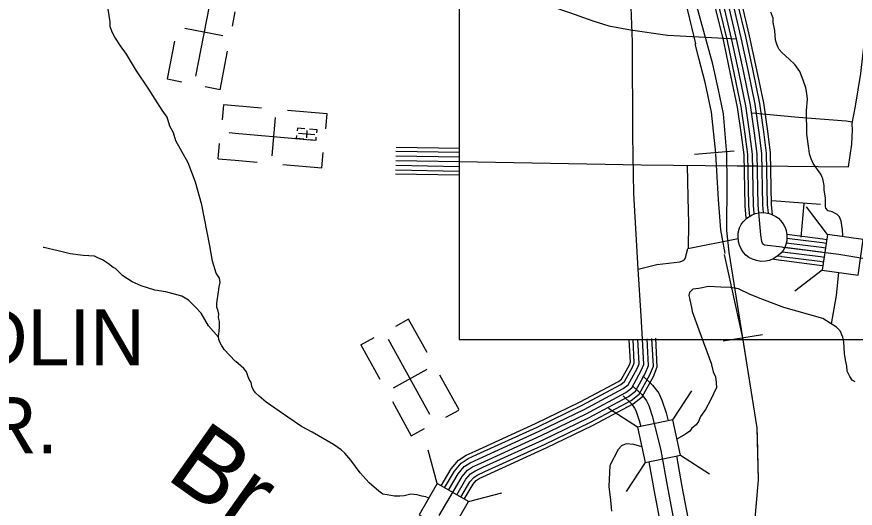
# Model space of a CAD drawing. Extents: x 1551132 to 1791609, y 378168 to 563823.
# Drawn here: x 1670772 to 1676283, y 417031 to 420262 of the extents above; entities that cross this region are included whole.
import ezdxf

# ---------------------------------------------------------------- set-up
doc = ezdxf.new("R2010")
doc.units = 0
for name, color, linetype in [('DESIGN - CONTOURS - Intermediate with optional Text', 7, 'Continuous'), ('DESIGN - DRAINAGE - Bridges and Cross Drains Size Text', 7, 'Continuous'), ('DESIGN - ROW - Right-of-Way and Easement Labels', 7, 'Continuous'), ('DESIGN - ROW - Right-of-Way Linework', 7, 'Continuous'), ('DESIGN - TRANSPORTATION - Text', 7, 'Continuous'), ('DESIGN - UTILITIES - Cable (Underground) with Text', 7, 'Continuous'), ('SURVEY - CONTOURS - Index with Text', 7, 'Continuous'), ('SURVEY - CONTROL with Text', 7, 'Continuous'), ('SURVEY - DRAINAGE - Storm Sewer', 7, 'Continuous'), ('SURVEY - PROPERTY - Owners', 7, 'Continuous'), ('SURVEY - TRANSPORTATION - Roads', 7, 'Continuous'), ('SURVEY - VEGETATION - Features with Text', 7, 'Continuous')]:
    doc.layers.add(name, color=color, linetype=linetype)

msp = doc.modelspace()

# ---------------------------------------------------------------- linework, layer by layer
at = {"layer": 'DESIGN - CONTOURS - Intermediate with optional Text'}
for p, q in [((1675486.076, 419377.968), (1675226.932, 419357.05)), ((1675672.062, 418170.744), (1675415.335, 418129.685))]:
    msp.add_line(p, q, dxfattribs=at)
for points in [[(1675453.401, 418714.959), (1675438.401, 418857.054), (1675440.785, 419175.754), (1675438.56, 419361.426), (1675417.361, 419624.074), (1675385.011, 419780.695), (1675346.787, 419949.399), (1675252.39, 420293.033), (1675130.901, 420723.111), (1675084.952, 420917.95), (1675036.87, 421100.788), (1674986.772, 421281.651), (1674904.149, 421603.118), (1674796.101, 421980.952), (1674652.038, 422545.509), (1674573.44, 422868.926), (1674549.074, 423023.446), (1674520.9, 423196.043), (1674514.859, 423378.389), (1674515.025, 423580.703), (1674521.675, 423827.001), (1674529.617, 424193.477), (1674544.942, 425060.633), (1674568.509, 426136.02)], [(1675234.94, 420083.803), (1675182.025, 420302.134), (1675092.735, 420679.243)], [(1675367.228, 419364.317), (1675337.462, 419635.574), (1675297.78, 419820.821), (1675254.79, 419989.525), (1675231.632, 420083.803)], [(1675426.752, 418706.025), (1675400.294, 418861.504), (1675383.761, 419059.984), (1675367.228, 419361.009)], [(1675359.601, 414899.125), (1675337.41, 415069.646), (1675319.269, 415244.126), (1675316.728, 415380.363), (1675325.294, 415618.636), (1675345.61, 415832.725), (1675377.31, 415988.595), (1675442.158, 416248.244), (1675547.956, 416593.545), (1675612.388, 416812.05), (1675647.629, 417217.186), (1675638.121, 417559.67), (1675453.401, 418714.959)], [(1675543.699, 418150.211), (1675423.443, 418699.408)], [(1675639.838, 417497.718), (1675638.121, 417559.67), (1675543.699, 418150.211)], [(1675614.755, 416839.243), (1675647.629, 417217.186), (1675639.838, 417497.718)]]:
    msp.add_lwpolyline(points, dxfattribs=at)
at = {"layer": 'DESIGN - ROW - Right-of-Way Linework'}
msp.add_lwpolyline([(1673679.553, 422339.845), (1673679.551, 418141.276), (1676663.072, 418141.278), (1676663.074, 421138.773)], dxfattribs=at)
at = {"layer": 'DESIGN - TRANSPORTATION - Text'}
for points in [[(1672208.21, 417998.48), (1672135.828, 418074.648), (1672118.154, 418102.899), (1672108.337, 418119.041), (1672100.596, 418141.167), (1672096.804, 418159.234), (1672101.221, 418195.227), (1672103.554, 418223.236), (1672103.971, 418259.278), (1672098.271, 418285.387), (1672100.529, 418307.388), (1672092.854, 418335.514), (1672087.038, 418351.614), (1672087.363, 418379.64), (1672098.229, 418453.608), (1672102.629, 418487.593), (1672108.954, 418515.552), (1672105.279, 418543.636), (1672081.647, 418575.97), (1672058.555, 418654.355), (1672041.739, 418756.7), (1671988.857, 419025.698), (1671946.575, 419174.419), (1671898.035, 419301.181), (1671849.069, 419391.908), (1671817.695, 419446.359), (1671802.295, 419498.619), (1671778.804, 419542.97), (1671759.48, 419601.28), (1671728.005, 419647.731), (1671635.666, 419793.06), (1671558.959, 419906.155), (1671492.228, 420017.124), (1671452.854, 420071.684), (1671415.496, 420128.219), (1671399.863, 420160.453), (1671386.305, 420198.671), (1671384.655, 420228.73), (1671373.606, 420310.974)], [(1676202.792, 418816.337), (1676201.467, 418823.787), (1676198.375, 418861.571), (1676191.025, 418917.739), (1676179.351, 418945.915), (1676163.534, 418962.132), (1676131.719, 418978.549), (1676103.803, 418986.899), (1676089.986, 419003.092), (1676088.128, 419015.134), (1676086.778, 419071.227), (1676079.362, 419121.378), (1676077.737, 419153.445), (1676070.245, 419197.588), (1676056.595, 419227.797), (1676005.372, 419296.524), (1675993.747, 419328.708), (1675982.114, 419360.893), (1675978.514, 419394.985), (1675963.606, 419489.288), (1675961.423, 419645.517), (1675968.289, 419719.535), (1675964.731, 419757.628), (1675957.148, 419793.771), (1675939.748, 419846.047), (1675918.399, 419902.39), (1675884.925, 419948.858), (1675847.317, 419983.367), (1675801.802, 420025.985), (1675782.027, 420046.26), (1675776.186, 420060.344), (1675770.353, 420074.436), (1675758.745, 420108.629), (1675753.47, 420170.772), (1675744.095, 420224.957), (1675742.42, 420253.016), (1675726.887, 420293.259)], [(1672097.471, 418156.051), (1672031.606, 418230.136), (1671984.557, 418312.821), (1671947.016, 418353.339), (1671901.517, 418397.957), (1671855.81, 418424.558), (1671752.113, 418453.875), (1671680.223, 418464.775), (1671590.525, 418493.918), (1671530.793, 418518.685), (1671469.253, 418559.503), (1671419.804, 418608.17), (1671405.871, 418614.354), (1671374.113, 418636.771), (1671336.414, 418663.272), (1671304.573, 418677.689), (1671282.682, 418687.973), (1671208.717, 418692.889), (1671122.811, 418703.965), (1671045.013, 418722.948), (1670949.223, 418744.157), (1670946.107, 418745.007)], [(1676127.052, 418242.413), (1676159.334, 418429.493), (1676175.342, 418579.972)], [(1676282.756, 417861.22), (1676262.898, 417873.487), (1676247.174, 417897.713), (1676229.566, 417931.972), (1676227.941, 417964.031), (1676218.424, 418006.207), (1676212.916, 418048.333), (1676207.8, 418124.494), (1676202.15, 418154.603), (1676184.634, 418196.87), (1676158.909, 418221.221), (1676125.16, 418243.672), (1676069.545, 418278.397), (1675812.309, 418351.666), (1675686.82, 418399.275), (1675591.223, 418436.501), (1675515.624, 418473.486), (1675461.709, 418482.161), (1675399.719, 418484.928), (1675317.729, 418487.944), (1675255.572, 418476.694), (1675215.498, 418471.185), (1675193.232, 418449.427), (1675188.999, 418429.459), (1675192.79, 418411.384), (1675207.957, 418339.107), (1675211.381, 418324.032), (1675254.314, 418203.545), (1675337.428, 417977.789)], [(1673480.113, 417098.257), (1673461.013, 417107.04), (1673435.056, 417111.365), (1673403.148, 417119.766), (1673381.165, 417122.041), (1673361.183, 417124.291), (1673319.033, 417112.799), (1673289.009, 417111.165), (1673254.977, 417109.582), (1673207.086, 417120.191), (1673177.128, 417124.566), (1673151.329, 417142.908), (1673087.947, 417197.759), (1673028.707, 417264.578), (1672967.65, 417347.438), (1672928.176, 417393.981), (1672904.402, 417414.307), (1672882.586, 417430.59), (1672852.811, 417450.991), (1672713.698, 417530.809), (1672644.1, 417567.719), (1672552.785, 417628.92), (1672411.897, 417728.79), (1672364.331, 417767.424), (1672340.582, 417789.749), (1672324.84, 417811.975), (1672317.066, 417832.092), (1672311.391, 417860.201), (1672299.599, 417878.368), (1672289.883, 417902.519), (1672282.183, 417928.653), (1672264.409, 417948.895), (1672210.935, 417995.613), (1672208.21, 417998.48)], [(1675337.428, 417977.789), (1675338.478, 417973.172), (1675347.945, 417926.996), (1675363.986, 417893.812), (1675367.603, 417857.686), (1675371.211, 417825.177), (1675331.487, 417742.083), (1675298.987, 417680.673), (1675266.48, 417633.713), (1675252.038, 417601.204), (1675237.589, 417579.529), (1675207.606, 417558.245), (1675195.373, 417538.369), (1675167.132, 417518.694), (1675110.617, 417486.026)], [(1674879.789, 417434.483), (1674828.507, 417449.233), (1674776.391, 417453.7), (1674746.617, 417441.783), (1674724.284, 417417.958), (1674670.594, 417312.205), (1674663.369, 417174.934), (1674674.202, 417084.624), (1674681.427, 417012.372)]]:
    msp.add_lwpolyline(points, dxfattribs=at)
at = {"layer": 'DESIGN - UTILITIES - Cable (Underground) with Text'}
for p, q in [((1672189.87, 420200.913), (1672208.211, 420295.307)), ((1672126.471, 420137.419), (1671877.527, 420185.82)), ((1671807.479, 420100.943), (1671759.471, 419854.137)), ((1672108.43, 419782.243), (1672157.712, 420035.6)), ((1671759.605, 419854.095), (1671856.094, 419835.353)), ((1672108.255, 419782.327), (1672010.624, 419801.252)), ((1672130.546, 419683.449), (1672121.921, 419585.547)), ((1672208.211, 419676.816), (1672130.504, 419683.624)), ((1672380.99, 419661.665), (1672208.211, 419676.816)), ((1672811.213, 419624.131), (1672551.311, 419646.707)), ((1672450.73, 419348.115), (1672472.688, 419600.764)), ((1672802.455, 419524.737), (1672811.172, 419623.473)), ((1672616.709, 419530.002), (1672615.076, 419511.461)), ((1672664.141, 419525.878), (1672616.701, 419530.035)), ((1672610.085, 419462.903), (1672611.71, 419481.686)), ((1672677.35, 419466.496), (1672681.508, 419514.345)), ((1672745.623, 419518.771), (1672696.399, 419523.045)), ((1672743.965, 419499.946), (1672745.615, 419518.646)), ((1672095.572, 419329.148), (1672104.146, 419428.326)), ((1672610.06, 419462.853), (1672658.776, 419458.612)), ((1672690.542, 419455.83), (1672738.966, 419451.597)), ((1672738.974, 419451.58), (1672740.599, 419470.397)), ((1672776.097, 419269.347), (1672784.68, 419368.708)), ((1672095.438, 419328.881), (1672208.211, 419319.065)), ((1672208.211, 419319.065), (1672352.657, 419306.489)), ((1672520.378, 419291.789), (1672776.056, 419269.439)), ((1673347.04, 418274.581), (1673261.063, 418226.795)), ((1673468.97, 418054.66), (1673347.215, 418274.489)), ((1673033.667, 418105.307), (1673120.652, 418153.617)), ((1673033.617, 418105.215), (1673158.714, 417879.536)), ((1673247.992, 417821.635), (1673469.763, 417944.616)), ((1673678.462, 417677.003), (1673551.957, 417905.107)), ((1673240.251, 417732.225), (1673364.823, 417507.688)), ((1673591.119, 417628.826), (1673677.804, 417676.695)), ((1673364.598, 417507.596), (1673451.9, 417556.131))]:
    msp.add_line(p, q, dxfattribs=at)
for points in [[(1672054.573, 420424.085), (1671947.175, 419871.429)], [(1672208.211, 419495.153), (1672167.328, 419498.728)], [(1672728.232, 419449.668), (1672208.211, 419495.153)], [(1672729.907, 419485.729), (1672623.676, 419495.02)], [(1673487.366, 417648.225), (1673214.421, 418140.726)]]:
    msp.add_lwpolyline(points, dxfattribs=at)
at = {"layer": 'SURVEY - CONTOURS - Index with Text'}
for points in [[(1673679.552, 420476.829), (1673736.792, 420462.762), (1674021.052, 420401.994), (1674275.163, 420333.484), (1674405.143, 420290.191), (1674559.081, 420234.648), (1674663.079, 420201.614), (1674805.259, 420176.23), (1675047.645, 420141.896), (1675502.751, 420117.587)], [(1674981.687, 418634.273), (1675129.959, 418650.74), (1675142.958, 418655.199), (1675156.125, 418661.782), (1675159.683, 418665.982), (1675163.766, 418672.674), (1675168.366, 418683.708), (1675173.799, 418705.017), (1675182.924, 418739.667), (1675513.45, 418805.294)], [(1674884.172, 418143.452), (1674876.039, 418296.172), (1674856.832, 418602.905), (1674987.512, 418635.74)], [(1673547.986, 416982.245), (1673698.808, 417239.294), (1673733.299, 417281.053), (1673767.598, 417302.771), (1673821.997, 417328.305), (1674218.829, 417508.91), (1674515.022, 417652.389), (1674775.075, 417792.209), (1674813.466, 417821.902), (1674876.706, 417935.513), (1674893.122, 417975.431), (1674884.172, 418143.452)], [(1673562.211, 417177.834), (1673627.535, 417289.17), (1673675.242, 417346.93), (1673725.816, 417378.956), (1673785.614, 417407.023), (1674181.964, 417587.412), (1674475.573, 417729.632), (1674727.701, 417865.194), (1674746.35, 417879.62), (1674798.449, 417973.222), (1674805.491, 417990.339), (1674797.583, 418138.835)], [(1673583.627, 417165.517), (1673647.843, 417274.953), (1673691.792, 417328.155), (1673737.724, 417357.239), (1673795.981, 417384.59), (1674192.472, 417565.036), (1674486.815, 417707.615), (1674741.201, 417844.394), (1674765.475, 417863.169), (1674820.757, 417962.472), (1674830.465, 417986.089), (1674822.265, 418140.152)], [(1673610.468, 417149.992), (1673673.325, 417257.119), (1673712.541, 417304.604), (1673752.665, 417330.005), (1673808.989, 417356.447), (1674205.646, 417536.969), (1674500.923, 417680.006), (1674758.142, 417818.301), (1674789.474, 417842.535), (1674848.731, 417948.997), (1674861.798, 417980.756), (1674853.215, 418141.802)], [(1673637.318, 417134.5), (1673698.808, 417239.294), (1673733.299, 417281.053), (1673767.598, 417302.771), (1673821.997, 417328.305), (1674218.829, 417508.91), (1674515.022, 417652.389), (1674775.075, 417792.209), (1674813.466, 417821.902), (1674876.706, 417935.513), (1674893.122, 417975.431), (1674884.172, 418143.452)], [(1673664.175, 417119.016), (1673724.291, 417221.469), (1673754.057, 417257.503), (1673782.531, 417275.537), (1673835.005, 417300.162), (1674232.012, 417480.851), (1674529.122, 417624.771), (1674792.008, 417766.117), (1674837.457, 417801.268), (1674904.68, 417922.029), (1674924.446, 417970.105), (1674915.13, 418145.102)], [(1673691.008, 417103.482), (1673749.773, 417203.635), (1673774.806, 417233.952), (1673797.472, 417248.303), (1673848.013, 417272.02), (1674245.187, 417452.783), (1674543.23, 417597.162), (1674808.949, 417740.024), (1674861.456, 417780.634), (1674932.654, 417908.554), (1674955.779, 417964.772), (1674946.079, 418146.752)], [(1673713.266, 417090.607), (1673770.906, 417188.843), (1673792.031, 417214.418), (1673809.864, 417225.71), (1673858.796, 417248.678), (1674256.12, 417429.508), (1674554.93, 417574.253), (1674822.999, 417718.382), (1674881.356, 417763.517), (1674955.862, 417897.362), (1674981.762, 417960.355), (1674971.762, 418148.119)]]:
    msp.add_lwpolyline(points, dxfattribs=at)
at = {"layer": 'SURVEY - CONTROL with Text'}
for points in [[(1675565.173, 418937.756), (1675558.399, 419019.817), (1675551.532, 419354.751), (1675535.391, 419485.921), (1675509.525, 419666.975), (1675465.985, 419876.781), (1675418.194, 420098.337), (1675369.162, 420303.009), (1675305.514, 420572.232), (1675177.867, 421025.519), (1675154.059, 421147.472), (1675081.686, 421563.05), (1674910.882, 422636.803)], [(1675589.031, 418949.09), (1675583.09, 419021.083), (1675576.215, 419356.517), (1675559.899, 419489.179), (1675533.883, 419671.242), (1675490.167, 419881.898), (1675442.294, 420103.828), (1675393.203, 420308.725), (1675329.446, 420578.433), (1675201.933, 421031.253), (1675178.359, 421151.964), (1675106.069, 421567.108), (1674935.29, 422640.686)], [(1675618.614, 418967.59), (1675614.064, 419022.683), (1675607.181, 419358.734), (1675590.623, 419493.271), (1675564.432, 419676.584), (1675520.5, 419888.315), (1675472.526, 420110.704), (1675423.361, 420315.909), (1675359.462, 420586.199), (1675232.116, 421038.436), (1675208.85, 421157.589), (1675136.643, 421572.209), (1674965.906, 422645.562)], [(1675808.576, 418745.785), (1675802.601, 418746.551), (1675686.721, 418761.41), (1675680.537, 418764.443), (1675677.121, 418767.86), (1675672.429, 418774.694), (1675668.879, 418783.619), (1675661.263, 418827.77), (1675645.038, 419024.275), (1675638.139, 419360.951), (1675621.356, 419497.354), (1675594.981, 419681.934), (1675550.824, 419894.731), (1675502.751, 420117.587), (1675453.518, 420323.084), (1675389.478, 420593.975), (1675262.298, 421045.62), (1675239.332, 421163.223), (1675167.226, 421577.3), (1674996.522, 422650.428), (1674996.522, 422650.428)], [(1675649.313, 418972.457), (1675645.038, 419024.275), (1675638.139, 419360.951), (1675621.356, 419497.354), (1675594.981, 419681.934), (1675550.824, 419894.731), (1675502.751, 420117.587), (1675453.518, 420323.084), (1675389.478, 420593.975), (1675262.298, 421045.62), (1675239.332, 421163.223), (1675167.226, 421577.3), (1674996.522, 422650.428)], [(1675680.312, 418973.816), (1675676.013, 419025.867), (1675669.096, 419363.167), (1675652.088, 419501.438), (1675625.531, 419687.284), (1675581.149, 419901.148), (1675532.975, 420124.471), (1675483.676, 420330.259), (1675419.494, 420601.75), (1675292.481, 421052.803), (1675269.815, 421168.856), (1675197.808, 421582.392), (1675027.138, 422655.295)], [(1675711.728, 418970.065), (1675706.987, 419027.467), (1675700.062, 419365.384), (1675682.813, 419505.53), (1675656.08, 419692.626), (1675611.481, 419907.565), (1675563.207, 420131.346), (1675513.834, 420337.443), (1675449.51, 420609.517), (1675322.664, 421059.987), (1675300.306, 421174.482), (1675228.383, 421587.492), (1675057.754, 422660.17)], [(1675738.436, 418959.099), (1675732.678, 419028.784), (1675725.745, 419367.226), (1675708.312, 419508.913), (1675681.421, 419697.068), (1675636.639, 419912.89), (1675588.282, 420137.054), (1675538.85, 420343.393), (1675474.41, 420615.967), (1675347.696, 421065.945), (1675325.589, 421179.157), (1675253.749, 421591.717), (1675083.145, 422664.212)], [(1676068.953, 418799.82), (1675832.859, 418830.095)], [(1676061.862, 418744.56), (1675828.601, 418774.477)], [(1676065.803, 418775.311), (1675833.292, 418805.128)], [(1676091.069, 418772.069), (1676065.787, 418775.311)], [(1676094.528, 418796.536), (1676068.937, 418799.82)], [(1675804.634, 418715.034), (1675800.735, 418715.534)], [(1676053.979, 418683.058), (1675804.634, 418715.034)], [(1676411.912, 418660.433), (1676175.576, 418698.717), (1675808.576, 418745.785)], [(1676057.92, 418713.809), (1675820.334, 418744.276)], [(1676082.461, 418710.659), (1676057.903, 418713.809)], [(1676086.761, 418741.36), (1676061.845, 418744.56)], [(1675797.543, 418659.774), (1675791.568, 418660.541), (1675737.869, 418667.424)], [(1675800.685, 418684.291), (1675794.71, 418685.05), (1675771.169, 418688.066)], [(1676046.762, 418626.798), (1675797.418, 418658.774)], [(1676050.037, 418652.307), (1675800.693, 418684.283)], [(1676073.811, 418649.257), (1676050.02, 418652.307)], [(1676078.136, 418679.958), (1676053.962, 418683.058)], [(1676070.236, 418623.79), (1676046.745, 418626.807)]]:
    msp.add_lwpolyline(points, dxfattribs=at)
at = {"layer": 'SURVEY - DRAINAGE - Storm Sewer'}
for p, q in [((1676099.347, 418830.873), (1675962.65, 419012.27)), ((1676066.277, 418595.588), (1675884.889, 418458.9)), ((1675084.774, 417612.82), (1675208.495, 417803.323)), ((1674852.367, 417563.431), (1674661.939, 417687.11)), ((1673535.373, 417193.313), (1673476.593, 417412.703)), ((1675134.197, 417380.404), (1675324.7, 417256.725)), ((1674901.773, 417331.057), (1674778.086, 417140.553)), ((1673741.143, 417074.526), (1673960.509, 417133.315))]:
    msp.add_line(p, q, dxfattribs=at)
for points in [[(1676066.277, 418595.588), (1676301.579, 418562.527), (1676334.631, 418797.812), (1676099.347, 418830.873)], [(1674852.367, 417563.431), (1674901.798, 417330.982), (1675134.197, 417380.404), (1675084.774, 417612.82)], [(1673416.578, 416987.534), (1673622.356, 416868.739), (1673741.143, 417074.526), (1673535.373, 417193.313)]]:
    msp.add_lwpolyline(points, close=True, dxfattribs=at)
at = {"layer": 'SURVEY - PROPERTY - Owners'}
for points in [[(1674885.739, 417902.52), (1674950.121, 417840.752), (1674991.353, 417787.051), (1675012.502, 417742.5), (1675040.735, 417659.214), (1675053.96, 417606.238)], [(1674820.465, 417834.477), (1674879.689, 417777.659), (1674910.472, 417737.566), (1674924.971, 417707.024), (1674950.196, 417632.613), (1675005.852, 417409.616), (1675051.176, 417156.701), (1675126.874, 416749.19)], [(1674757.675, 417769.017), (1674811.932, 417716.957), (1674832.665, 417689.965), (1674840.765, 417672.898), (1674863.089, 417607.021), (1674872.856, 417567.895)], [(1674926.838, 417336.339), (1674961.945, 417140.417), (1675010.985, 416876.41), (1675037.343, 416734.49), (1675047.943, 416660.246), (1675051.043, 416627.479), (1675049.168, 416600.436), (1675028.343, 416512.134), (1675003.735, 416428.423), (1674951.978, 416252.36), (1674909.771, 416100.598), (1674879.28, 415975.911), (1674872.547, 415934.544), (1674862.638, 415873.734)], [(1675107.9, 417374.715), (1675143.932, 417173.626), (1675192.873, 416910.203), (1675219.939, 416764.466), (1675231.697, 416682.047), (1675236.647, 416629.795), (1675232.672, 416572.611), (1675207.247, 416464.783), (1675181.223, 416376.247), (1675129.849, 416201.476), (1675088.783, 416053.822), (1675060.7, 415939.01), (1675055.134, 415904.801), (1675050.076, 415873.734)]]:
    msp.add_lwpolyline(points, dxfattribs=at)
at = {"layer": 'SURVEY - TRANSPORTATION - Roads'}
for points in [[(1674856.832, 418602.905), (1674827.841, 419100.302), (1674819.925, 419480.987), (1674818.55, 420097.953), (1674805.017, 420441.062), (1674785.176, 420500.605), (1674758.718, 420570.074), (1674725.652, 420646.159), (1674591.672, 420890.649)], [(1676261.349, 419561.206), (1676283.307, 419674.218), (1676319.656, 419890.132), (1676354.997, 420198.19), (1676373.855, 420276.092), (1676396.288, 420351.56)], [(1676263.016, 419569.798), (1676222.183, 419574.782), (1675910.182, 419600.457), (1675602.556, 419628.899)], [(1676239, 419275.915), (1676260.732, 419423.894), (1676263.616, 419518.205), (1676262.299, 419553.856), (1676261.349, 419561.206)], [(1673264.203, 419379.083), (1673680.693, 419371.583)], [(1673264.669, 419404.792), (1673681.159, 419397.292)], [(1673263.086, 419317.09), (1673679.576, 419309.59)], [(1673263.086, 419317.09), (1673679.576, 419309.59)], [(1673263.644, 419348.083), (1673680.134, 419340.583)], [(1673679.576, 419309.59), (1674877.906, 419288.007), (1675506.408, 419282.674), (1675639.664, 419281.44)], [(1673261.969, 419255.097), (1673678.459, 419247.597)], [(1673262.528, 419286.098), (1673679.018, 419278.598)], [(1675185.757, 418740.234), (1675187.924, 418905.255), (1675183.949, 419073.085), (1675180.441, 419285.44)], [(1675639.664, 419281.44), (1676239, 419275.915)], [(1673261.528, 419230.388), (1673678.018, 419222.888)], [(1675734.828, 419055.176), (1676054.062, 419030.392)], [(1675944.965, 419031.434), (1675925.732, 418812.286)]]:
    msp.add_lwpolyline(points, dxfattribs=at)
at = {"layer": 'SURVEY - VEGETATION - Features with Text'}
msp.add_lwpolyline([(1675546.549, 418913.922), (1675557.265, 418924.948), (1675571.065, 418938.24), (1675587.065, 418948.923), (1675605.031, 418959.023), (1675628.039, 418968.365), (1675650.163, 418972.574), (1675668.021, 418974.516), (1675695.137, 418973.174), (1675713.987, 418969.207), (1675729.186, 418963.84), (1675747.069, 418956.19), (1675761.702, 418948.157), (1675777.277, 418937.165), (1675791.668, 418923.406), (1675802.926, 418908.606), (1675812.376, 418892.647), (1675821.867, 418876.646), (1675828.492, 418855.963), (1675832.967, 418828.778), (1675833.634, 418809.603), (1675831.959, 418788.144), (1675826.417, 418765.277), (1675820.876, 418745.143), (1675808.768, 418726.226), (1675793.976, 418707.084), (1675776.502, 418691.9), (1675755.036, 418676.224), (1675735.236, 418665.766), (1675715.87, 418659.366), (1675694.862, 418654.707), (1675662.263, 418653.79), (1675633.563, 418658.732), (1675608.064, 418667.882), (1675583.898, 418680.333), (1675563.64, 418695.65), (1675547.774, 418711.259), (1675534.257, 418731.392), (1675521.858, 418761.377), (1675514.508, 418782.61), (1675512.95, 418815.886), (1675513.616, 418842.32), (1675522.991, 418873.78), (1675533.716, 418895.638)], close=True, dxfattribs=at)

# ---------------------------------------------------------------- texts
at = {"layer": 'DESIGN - DRAINAGE - Bridges and Cross Drains Size Text'}
msp.add_text('Br.', height=474.9965, rotation=324.668933, dxfattribs=at).set_placement((1671742.899, 417232.221))
at = {"layer": 'DESIGN - ROW - Right-of-Way and Easement Labels'}
for s, p in [('RANDLIN', (1669440.641, 417969.603)), ('DR.', (1670188.94, 417391.763))]:
    msp.add_text(s, height=369.9913, rotation=0.000028, dxfattribs=at).set_placement(p)

doc.saveas('drawing.dxf')
